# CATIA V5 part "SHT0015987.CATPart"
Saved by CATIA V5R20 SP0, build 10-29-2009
Part number: SHT0015987
Source: Unknown
Bounding box of the stored display mesh (mm): x -544 to 21.394, y -796.494 to -521.505, z -0.1 to 129.8
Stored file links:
  E:\杨逍\07-张甲\2023.10.9-A6座椅数据\2023.12.8-A6底支架图纸\SHT0015987-中宽车主驾驶底部支架焊接总成\SHT0015987.CATPart

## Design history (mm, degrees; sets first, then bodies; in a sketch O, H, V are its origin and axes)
AxisSystem1 "AXIS2_PLACEMENT_3D #26087": origin (6, -759.0091, 87.8), X (1, 0, 0), Y (0, 1, 0), Z (0, 0, 1)
Body1 "Q37108-焊接方螺母" (main body)
  Solid1: solid without history
Body2 "Q37108-焊接方螺母"
  Solid2: solid without history
Body3 "Q37108-焊接方螺母"
  Solid3: solid without history
Body4 "Q37108-焊接方螺母"
  Solid4: solid without history
Body5 "Q37108-焊接方螺母"
  Solid5: solid without history
Body6 "Q37108-焊接方螺母"
  Solid6: solid without history
Body7 "SHT0016190-支撑轴套"
  Solid7: solid without history
Body8 "SHT0016190-支撑轴套"
  Solid8: solid without history
Body9 "SHT0016190-支撑轴套"
  Solid9: solid without history
Body10 "SHT0016188-中宽车主驾驶前侧钣金"
  Solid10: solid without history
Body11 "Q37110-焊接方螺母"
  Solid11: solid without history
Body12 "Q37110-焊接方螺母"
  Solid12: solid without history
Body13 "Q37110-焊接方螺母"
  Solid13: solid without history
Body14 "SHT0016189-中宽车主驾驶后侧钣金"
  Solid14: solid without history
Body15 "SHT0016187-中宽车主驾驶右侧板金"
  Solid15: solid without history
Body16 "SHT0016185-中宽车主驾驶左侧板金"
  Solid16: solid without history
Body17 "中宽车主驾驶底部支架焊接总成-.1\\SHT0015987.1\\Q37108-焊接方螺母"
  Solid17: solid without history
Body18 "中宽车主驾驶底部支架焊接总成-.1\\几何体.15"
  Solid18: solid without history
  RemoveFace1: RemoveFaces (face of Solid18; face of Solid18; face of Solid18; face of Solid18; face of Solid18; face of Solid18; face of Solid18; face of Solid18)
  Sketch1 on face of Solid18, origin (0, 0, 2.9), H (1, 0, 0), V (0, 1, 0)
    point P1 (-518, -559.0004)
    point P2 (-530, -559.0004)
    point P3 (-530, -559.0004)
    point P4 (-518, -559.0004)
    arc A1 centre (-524, -559.0004) radius 6 from (-518, -559.0004) to (-530, -559.0004) ccw
    arc A2 centre (-524, -559.0004) radius 6 from (-530, -559.0004) to (-518, -559.0004) ccw
    coincidence: P1 P4, P2 P3
  Pocket1: profile Sketch1, direction (0, 0, -1), length 20, opposite side length 9
  RemoveFace2: RemoveFaces (face of Solid18; face of Solid18; face of Solid18; face of Solid18; face of Solid18; face of Solid18; face of Solid18; face of Solid18; face of Solid18; face of Solid18; face of Solid18; face of Solid18; face of Solid18; face of Solid18; face of Solid18; face of Solid18; face of Solid18; face of Solid18; face of Solid18; face of Solid18; face of Solid18; face of Solid18; face of Solid18; face of Solid18)
  Pocket2: profile Sketch3, direction (0, 1, 0), length -67, opposite side length -381
Body19 "中宽车主驾驶底部支架焊接总成-.1\\SHT0015987.1\\SHT0016190-支撑轴套"
  Solid19: solid without history
Body20 "中宽车主驾驶底部支架焊接总成-.1\\SHT0015987.1\\SHT0016190-支撑轴套"
  Solid20: solid without history
Body21 "中宽车主驾驶底部支架焊接总成-.1\\SHT0015987.1\\SHT0016190-支撑轴套"
  Solid21: solid without history
Body22 "中宽车主驾驶底部支架焊接总成-.1\\SHT0015987.1\\SHT0016188-中宽车主驾驶前侧钣金"
  Solid22: solid without history
Body23 "中宽车主驾驶底部支架焊接总成-.1\\SHT0015987.1\\Q37110-焊接方螺母"
  Solid23: solid without history
Body24 "中宽车主驾驶底部支架焊接总成-.1\\SHT0015987.1\\Q37110-焊接方螺母"
  Solid24: solid without history
Body25 "中宽车主驾驶底部支架焊接总成-.1\\SHT0015987.1\\Q37110-焊接方螺母"
  Solid25: solid without history
Body26 "中宽车主驾驶底部支架焊接总成-.1\\SHT0015987.1\\SHT0016189-中宽车主驾驶后侧钣金"
  Solid26: solid without history
Body27 "中宽车主驾驶底部支架焊接总成-.1\\几何体.17"
  Solid27: solid without history
  RemoveFace3: RemoveFaces (face of Solid27; face of Solid27; face of Solid27; face of Solid27; face of Solid27; face of Solid27; face of Solid27; face of Solid27; face of Solid27; face of Solid27; face of Solid27; face of Solid27; face of Solid27; face of Solid27; face of Solid27; face of Solid27; face of Solid27; face of Solid27; face of Solid27; face of Solid27; face of Solid27; face of Solid27; face of Solid27; face of Solid27; face of Solid27; face of Solid27; face of Solid27; face of Solid27; face of Solid27; face of Solid27; face of Solid27; face of Solid27)
  Sketch2 on face of Solid27, origin (0, 0, 2.9), H (1, 0, 0), V (0, 1, 0)
    point P1 (-518, -759.0091)
    point P2 (-530, -759.0091)
    point P3 (-530, -759.0091)
    point P4 (-518, -759.0091)
    arc A1 centre (-524, -759.0091) radius 6 from (-518, -759.0091) to (-530, -759.0091) ccw
    arc A2 centre (-524, -759.0091) radius 6 from (-530, -759.0091) to (-518, -759.0091) ccw
    coincidence: P1 P4, P2 P3
  Pocket3: profile Sketch2, direction (0, 0, -1), length 20, opposite side length 10
  Sketch3 on face of Solid27, origin (0, -796.4942, 0), H (1, 0, 0), V (0, 0, 1)
    circle A1 centre (-426.9101, 69.4154) radius 6
    circle A2 centre (-386.3597, 81.9779) radius 6
    circle A3 centre (-347.7815, 88.1914) radius 6
    radius A1 = 6
    radius A2 = 6
    radius A3 = 6
  Pocket4: profile Sketch3, direction (0, 1, 0), length -67, opposite side length -40
Body28 "中宽车主驾驶底部支架焊接总成-.1\\几何体.20"
  Solid28: solid without history
Body29 "中宽车主驾驶底部支架焊接总成-.1\\几何体.21"
  Solid29: solid without history
Body30 "中宽车主驾驶底部支架焊接总成-.1\\几何体.22"
  Solid30: solid without history
Body31 "中宽车主驾驶底部支架焊接总成-.1\\几何体.23"
  Solid31: solid without history
Body32 "中宽车主驾驶底部支架焊接总成-.1\\几何体.24"
  Solid32: solid without history
Body33 "中宽车主驾驶底部支架焊接总成-.1\\几何体.28"
  Solid33: solid without history
Body34 "中宽车主驾驶底部支架焊接总成-.1\\几何体.29"
  Solid34: solid without history
Body35 "中宽车主驾驶底部支架焊接总成-.1\\几何体.30"
  Solid35: solid without history
Body36 "中宽车主驾驶底部支架焊接总成-.1\\几何体.31"
  Solid36: solid without history
Body37 "中宽车主驾驶底部支架焊接总成-.1\\几何体.32"
  Solid37: solid without history
Body38 "中宽车主驾驶底部支架焊接总成-.1\\几何体.40"
  Solid38: solid without history
Body39 "中宽车主驾驶底部支架焊接总成-.1\\几何体.41"
  Solid39: solid without history
Body40 "中宽车主驾驶底部支架焊接总成-.1\\几何体.43"
  Solid40: solid without history
  Mirror1: of the body so far, about Plane1
  Set1
    Point1: type OnCurve, Support edge [face of Solid27 | face of Solid27], Ratio 0.5
    Plane1: type Normal, Curve edge [face of Solid27 | face of Solid27], RefPoint Point1
Body41 "中宽车主驾驶底部支架焊接总成-.1\\几何体.44"
  Solid41: solid without history
  Mirror2: of the body so far, about Plane2
  Set2
    Point2: type OnCurve, Support edge [face of Solid18 | face of Solid18], Ratio 0.5
    Plane2: type Normal, Curve edge [face of Solid18 | face of Solid18]
Body42 "中宽车主驾驶底部支架焊接总成-.1\\几何体.45"
  Solid42: solid without history
Body43 "中宽车主驾驶底部支架焊接总成-.1\\几何体.46"
  Solid43: solid without history
Body44 "中宽车主驾驶底部支架焊接总成-.1\\几何体.19"
  Solid44: solid without history
  Thickness1: Thickness -0.5, Face face of Solid44
Body45 "中宽车主驾驶底部支架焊接总成-.1\\几何体.48"
  Solid45: solid without history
